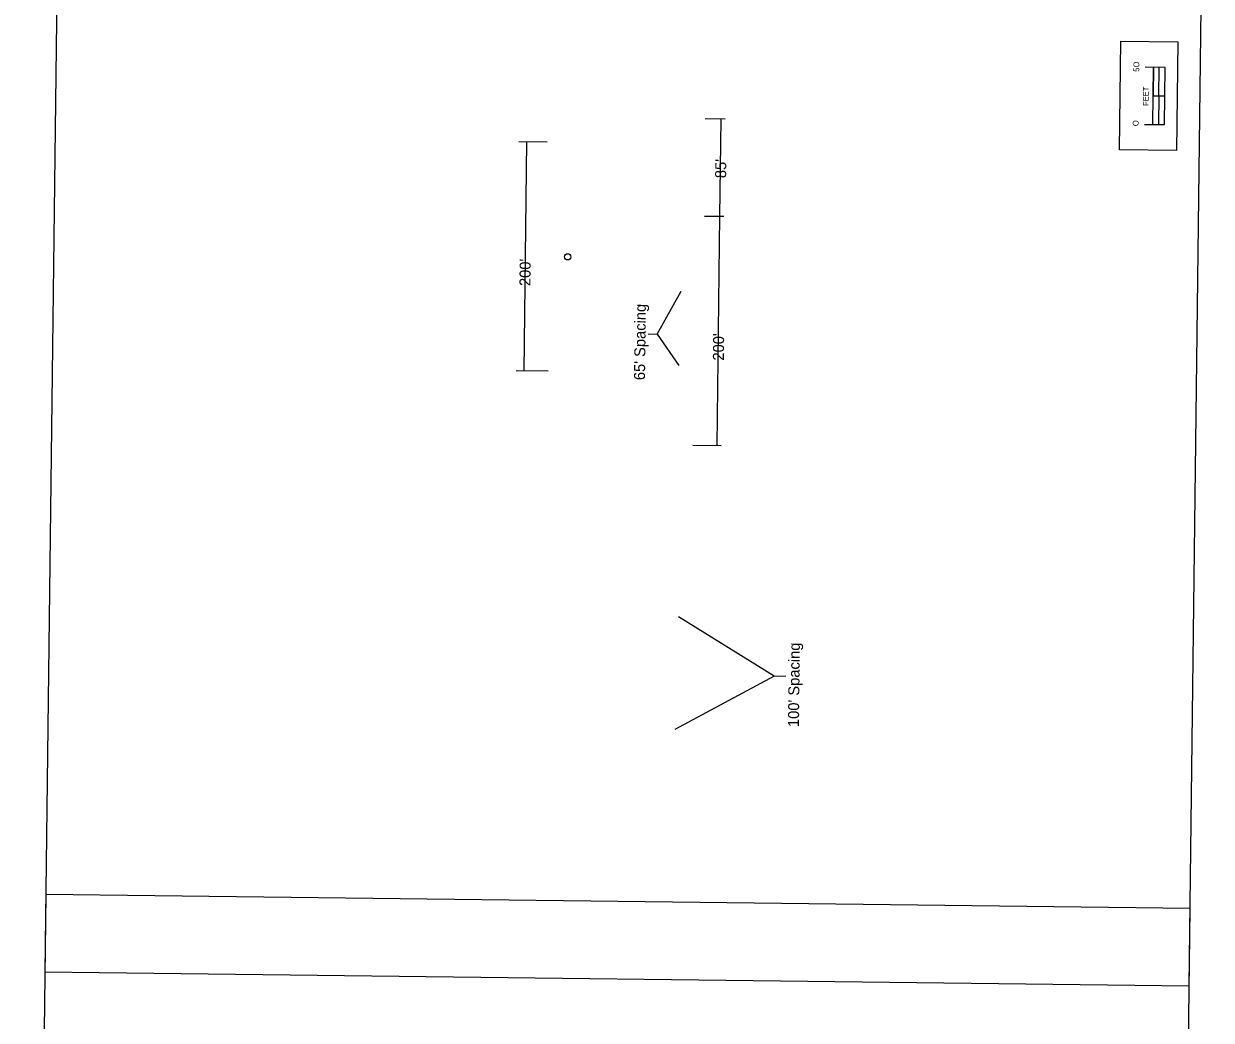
# Model space of a CAD drawing. Extents: x 4959127 to 4960275, y 3872379 to 3884458.
# Drawn here: x 4959200 to 4960238, y 3879849 to 3880719 of the extents above; entities that cross this region are included whole.
import ezdxf

# ---------------------------------------------------------------- set-up
doc = ezdxf.new("R2010")
doc.units = 0
for name, color, linetype in [('dsnCellElements', 7, 'Continuous'), ('dsnCellsScaleBlock', 7, 'Continuous'), ('NamedBoundary', 7, 'Continuous'), ('SheetText', 7, 'Continuous')]:
    doc.layers.add(name, color=color, linetype=linetype)

msp = doc.modelspace()

# ---------------------------------------------------------------- linework, layer by layer
at = {"layer": 'dsnCellElements'}
msp.add_lwpolyline([(4960157.7, 3880609.1), (4960158.9, 3880704.1), (4960208.9, 3880703.4), (4960207.7, 3880608.4)], close=True, dxfattribs=at)
msp.add_lwpolyline([(4960157.7, 3880609.1), (4960158.9, 3880704.1), (4960208.9, 3880703.4), (4960207.7, 3880608.4)], close=True, dxfattribs=at)
msp.add_circle((4959675.6, 3880515.6), 2.75, dxfattribs=at)
at = {"layer": 'dsnCellsScaleBlock'}
msp.add_line((4960197.3, 3880656.1), (4960187.3, 3880656.2), dxfattribs=at)
msp.add_line((4960197.3, 3880656.1), (4960187.3, 3880656.2), dxfattribs=at)
for points in [[(4960207.7, 3880608.4), (4960157.7, 3880609.1), (4960158.9, 3880704.1), (4960208.9, 3880703.4)], [(4960192.2, 3880656.1), (4960192.5, 3880681.1), (4960187.6, 3880681.2), (4960187.3, 3880656.2)], [(4960197, 3880631.1), (4960197.3, 3880656.1), (4960192.2, 3880656.1), (4960191.9, 3880631.1)]]:
    msp.add_lwpolyline(points, close=True, dxfattribs=at)
for points in [[(4960179.5, 3880631.3), (4960197, 3880631.1), (4960197.6, 3880681.1), (4960180.1, 3880681.3)], [(4960187, 3880631.2), (4960187.6, 3880681.2)]]:
    msp.add_lwpolyline(points, dxfattribs=at)
at = {"layer": 'NamedBoundary'}
for points in [[(4959218.8, 3879890.9), (4960218.7, 3879878.6), (4960238, 3881446), (4959238, 3881458.3)], [(4959200.4, 3878391), (4960200.4, 3878378.7), (4960219.6, 3879946.1), (4959219.6, 3879958.4)]]:
    msp.add_lwpolyline(points, close=True, dxfattribs=at)
at = {"layer": 'SheetText'}
for p, q in [((4959813.2, 3880635.9), (4959795.8, 3880636.2)), ((4959808.6, 3880551), (4959809.7, 3880636)), ((4959657.8, 3880615.9), (4959633.1, 3880616.2)), ((4959637.6, 3880415.9), (4959640.1, 3880616.1)), ((4959795.2, 3880551.2), (4959812.2, 3880551)), ((4959806.2, 3880350.8), (4959808.6, 3880551)), ((4959753.8, 3880448.1), (4959774.7, 3880485.7)), ((4959658.6, 3880415.6), (4959630.7, 3880416)), ((4959785.1, 3880351), (4959809.7, 3880350.7)), ((4959856.2, 3880149.1), (4959772.5, 3880201.1))]:
    msp.add_line(p, q, dxfattribs=at)
for points in [[(4959746, 3880448.2), (4959753.8, 3880448.1), (4959772.9, 3880420.7)], [(4959866.2, 3880149), (4959856.2, 3880149.1), (4959769.2, 3880102.5)]]:
    msp.add_lwpolyline(points, dxfattribs=at)

# ---------------------------------------------------------------- texts
at = {"layer": 'dsnCellsScaleBlock'}
for s, p in [('5O', (4960175, 3880677.3)), ('FEET', (4960183.2, 3880647.3)), ('O', (4960174.4, 3880629.7))]:
    msp.add_text(s, height=5, rotation=89.2975, dxfattribs=at).set_placement(p)
at = {"layer": 'SheetText'}
for s, rotation, p in [("85'", 89.3042, (4959814.1, 3880584.3)), ("200'", 89.3042, (4959643.1, 3880490)), ("65' Spacing", 89.3042, (4959743.2, 3880407.8)), ("200'", 89.2908, (4959812.1, 3880424.9)), ("100' Spacing", 89.3042, (4959877.7, 3880104.7))]:
    msp.add_text(s, height=9.6, rotation=rotation, dxfattribs=at).set_placement(p)

doc.saveas('drawing.dxf')
